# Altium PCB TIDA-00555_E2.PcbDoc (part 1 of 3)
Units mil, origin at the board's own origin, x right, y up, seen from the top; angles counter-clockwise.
Board outline 6490 x 3985 mil, 4 copper layers (Top Layer, MidLayer1, MidLayer2, Bottom Layer), stack 61.2 mil thick; 376 components, 194 nets, 936 pads, 294 vias.
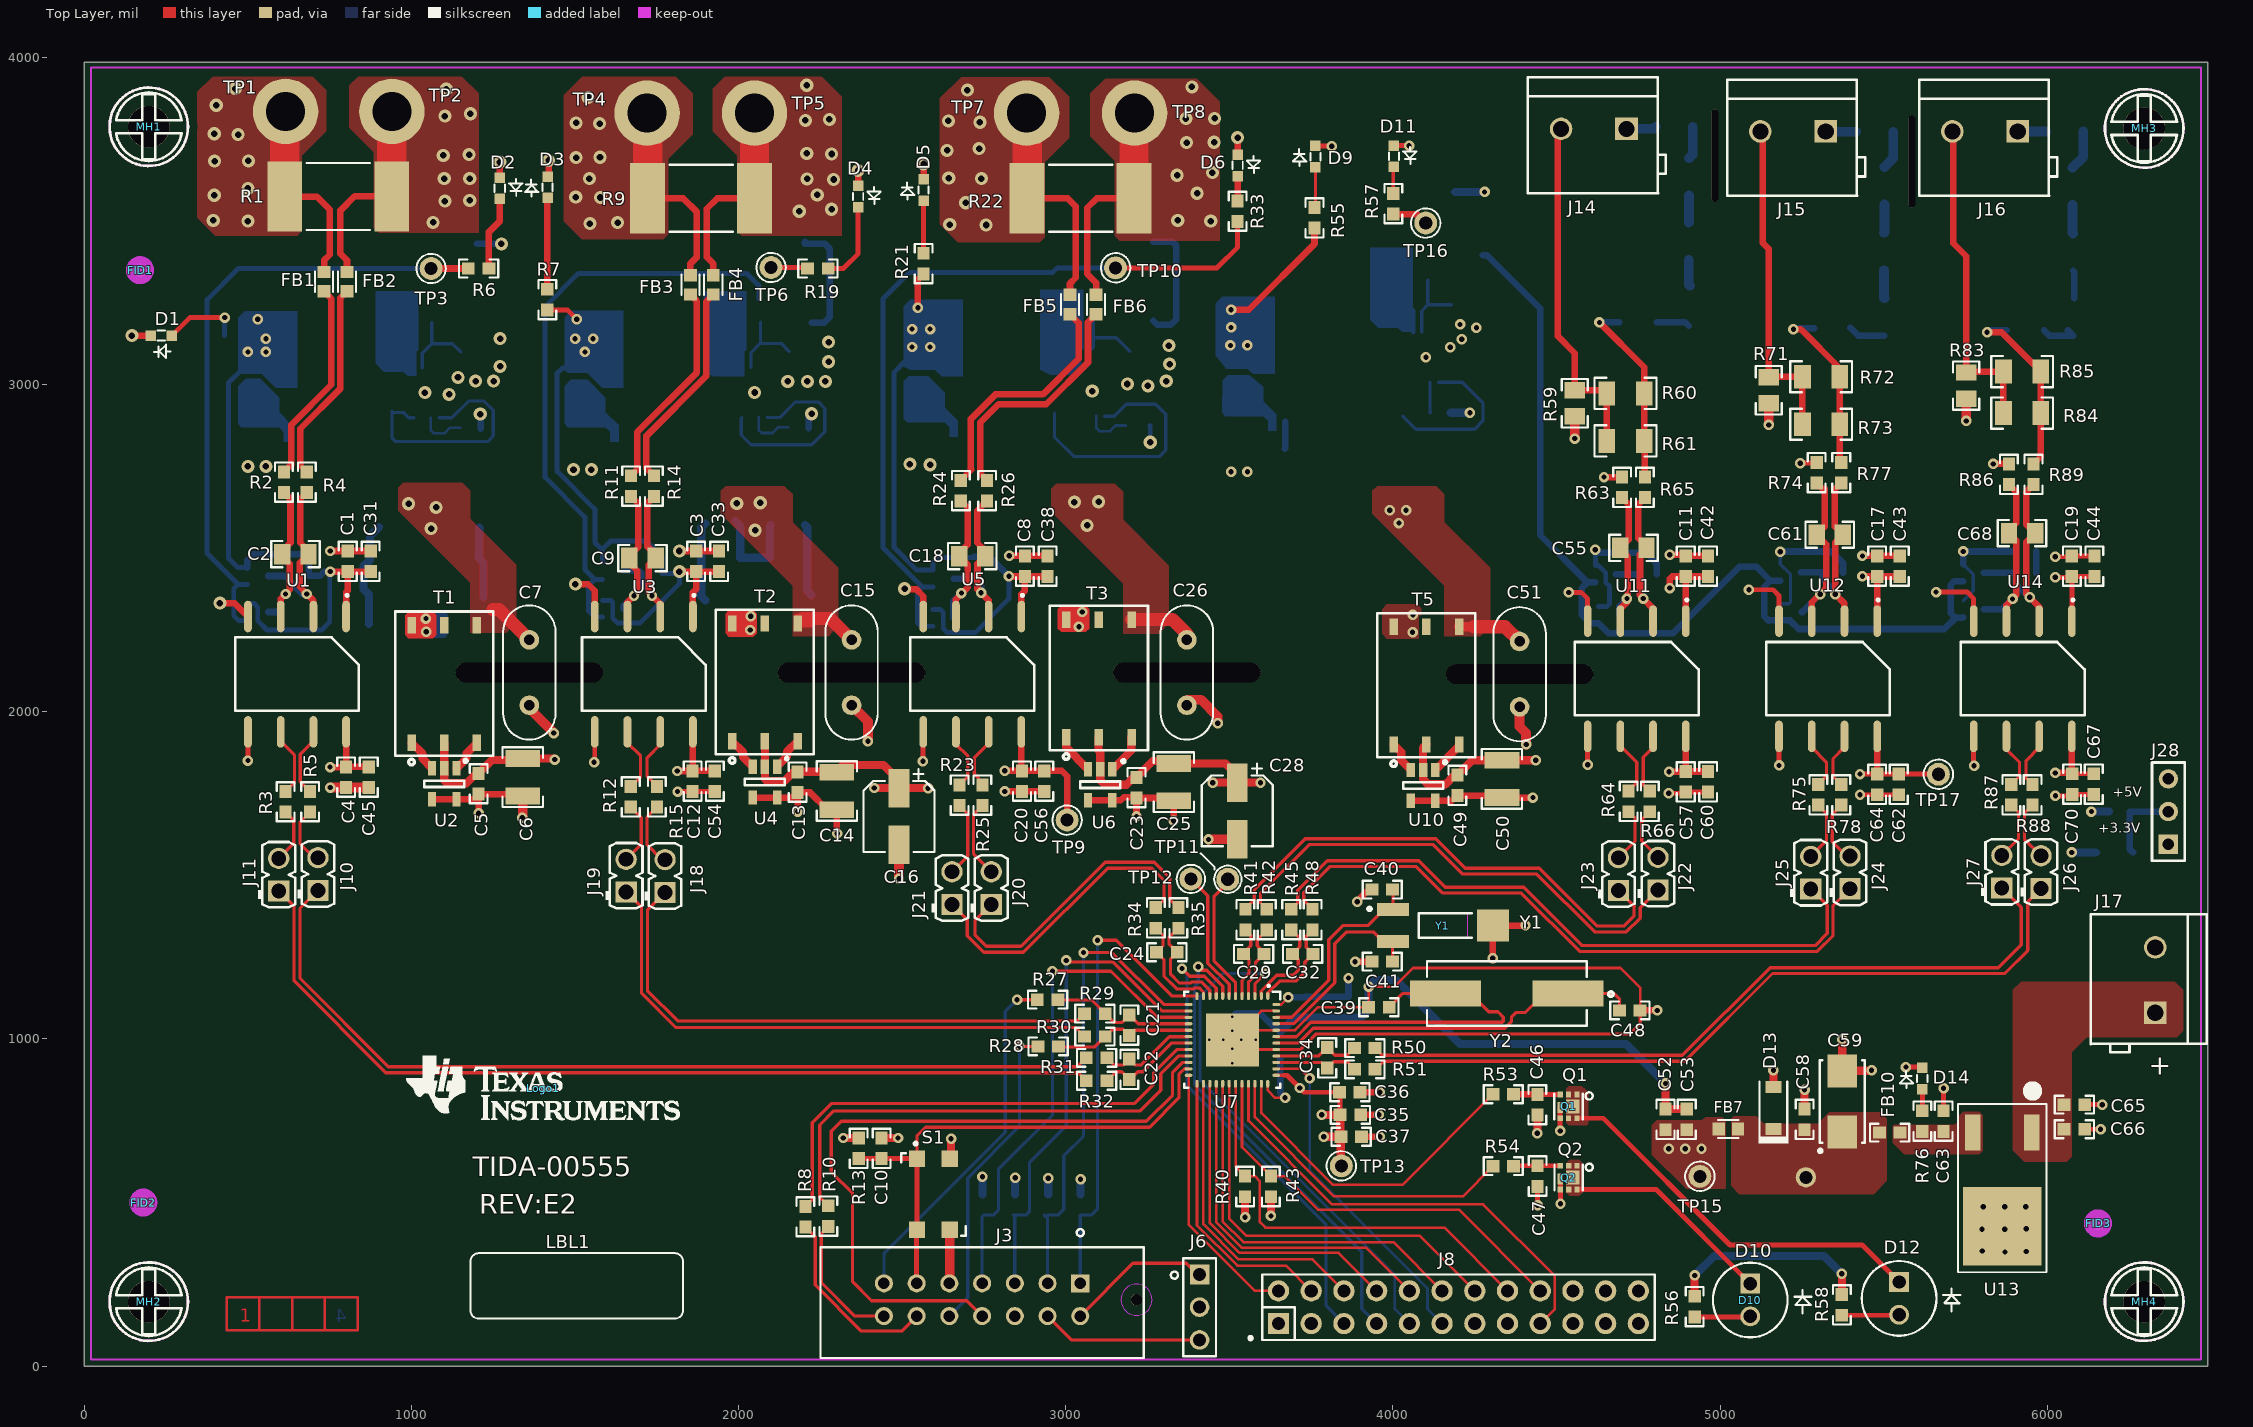
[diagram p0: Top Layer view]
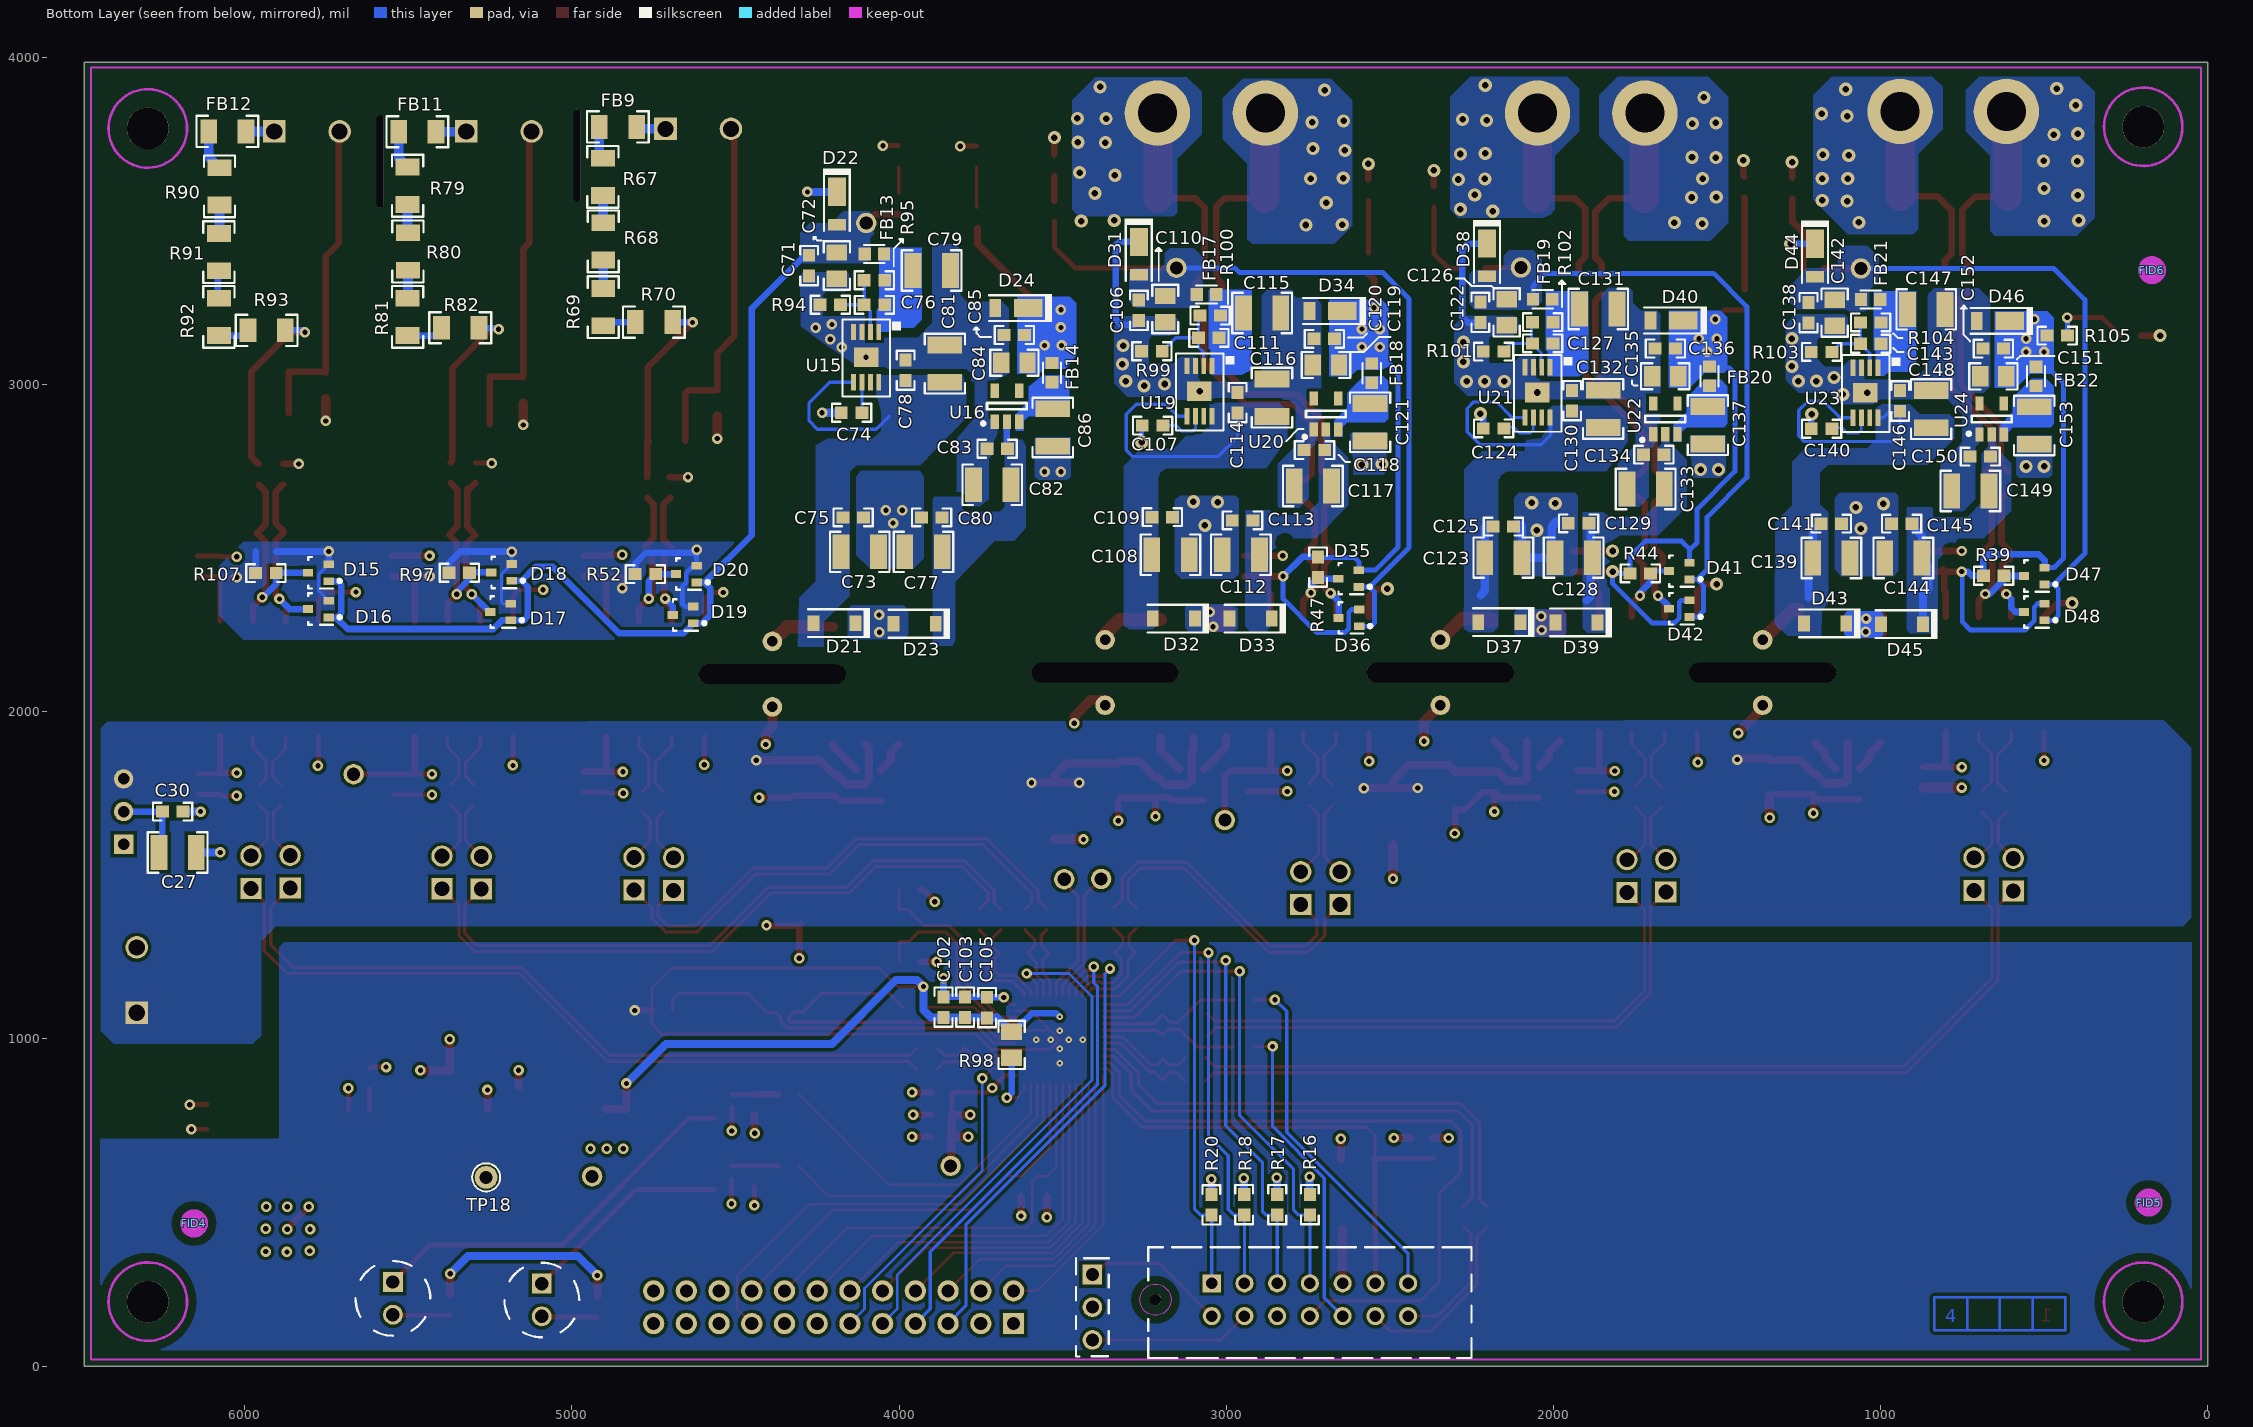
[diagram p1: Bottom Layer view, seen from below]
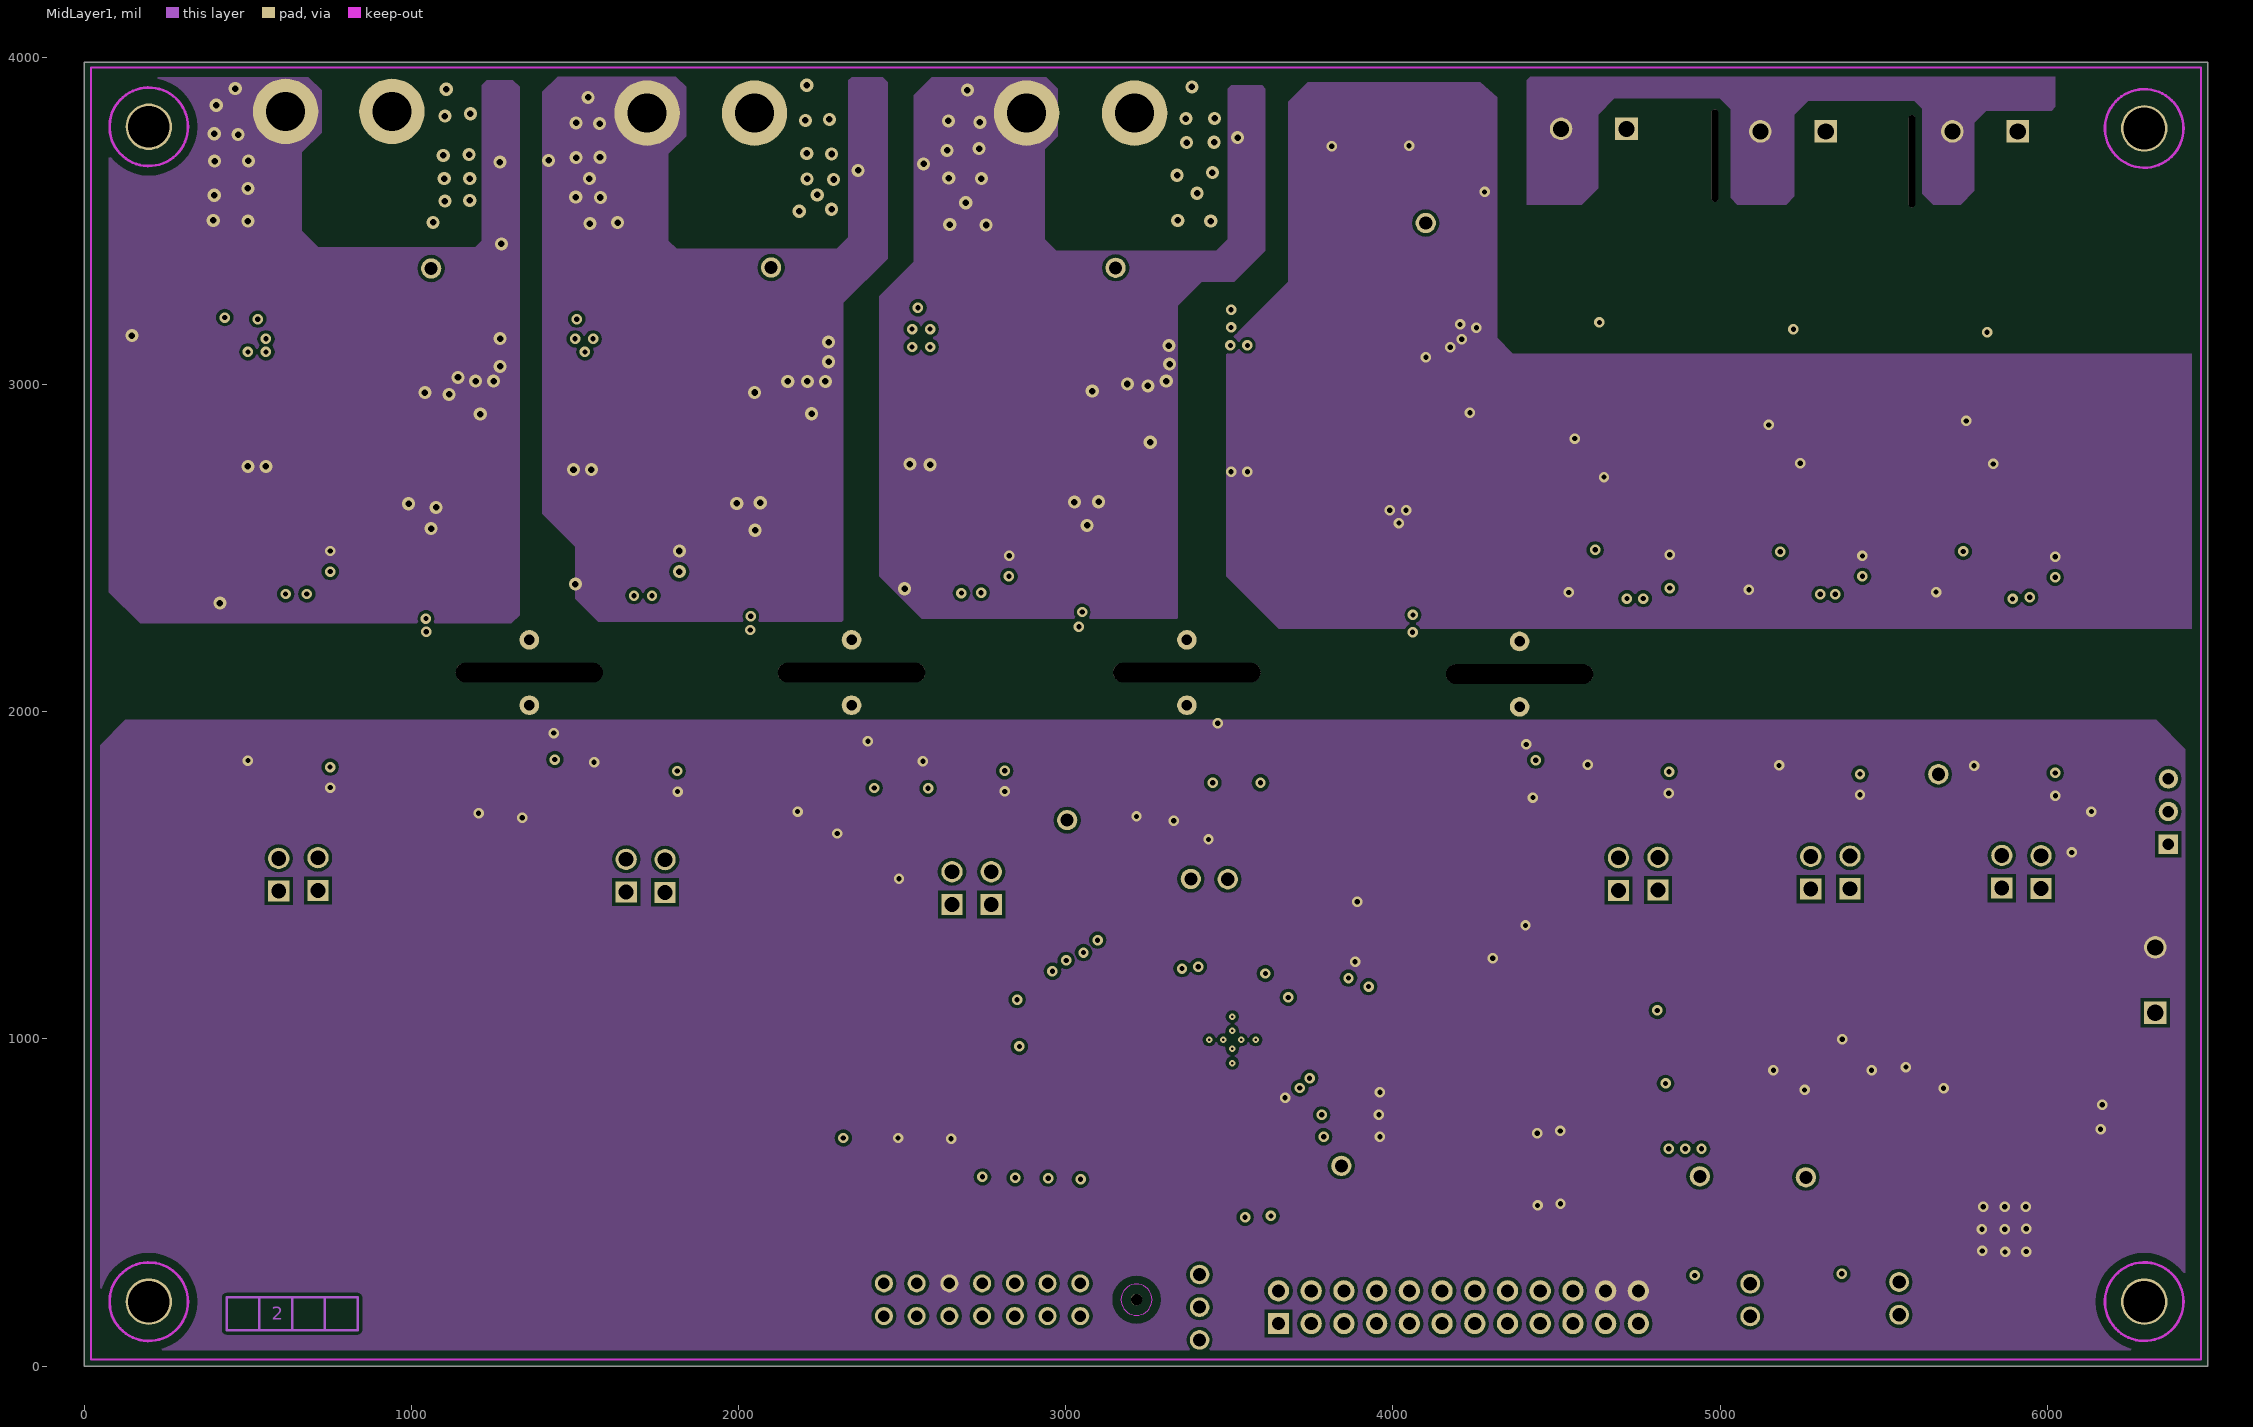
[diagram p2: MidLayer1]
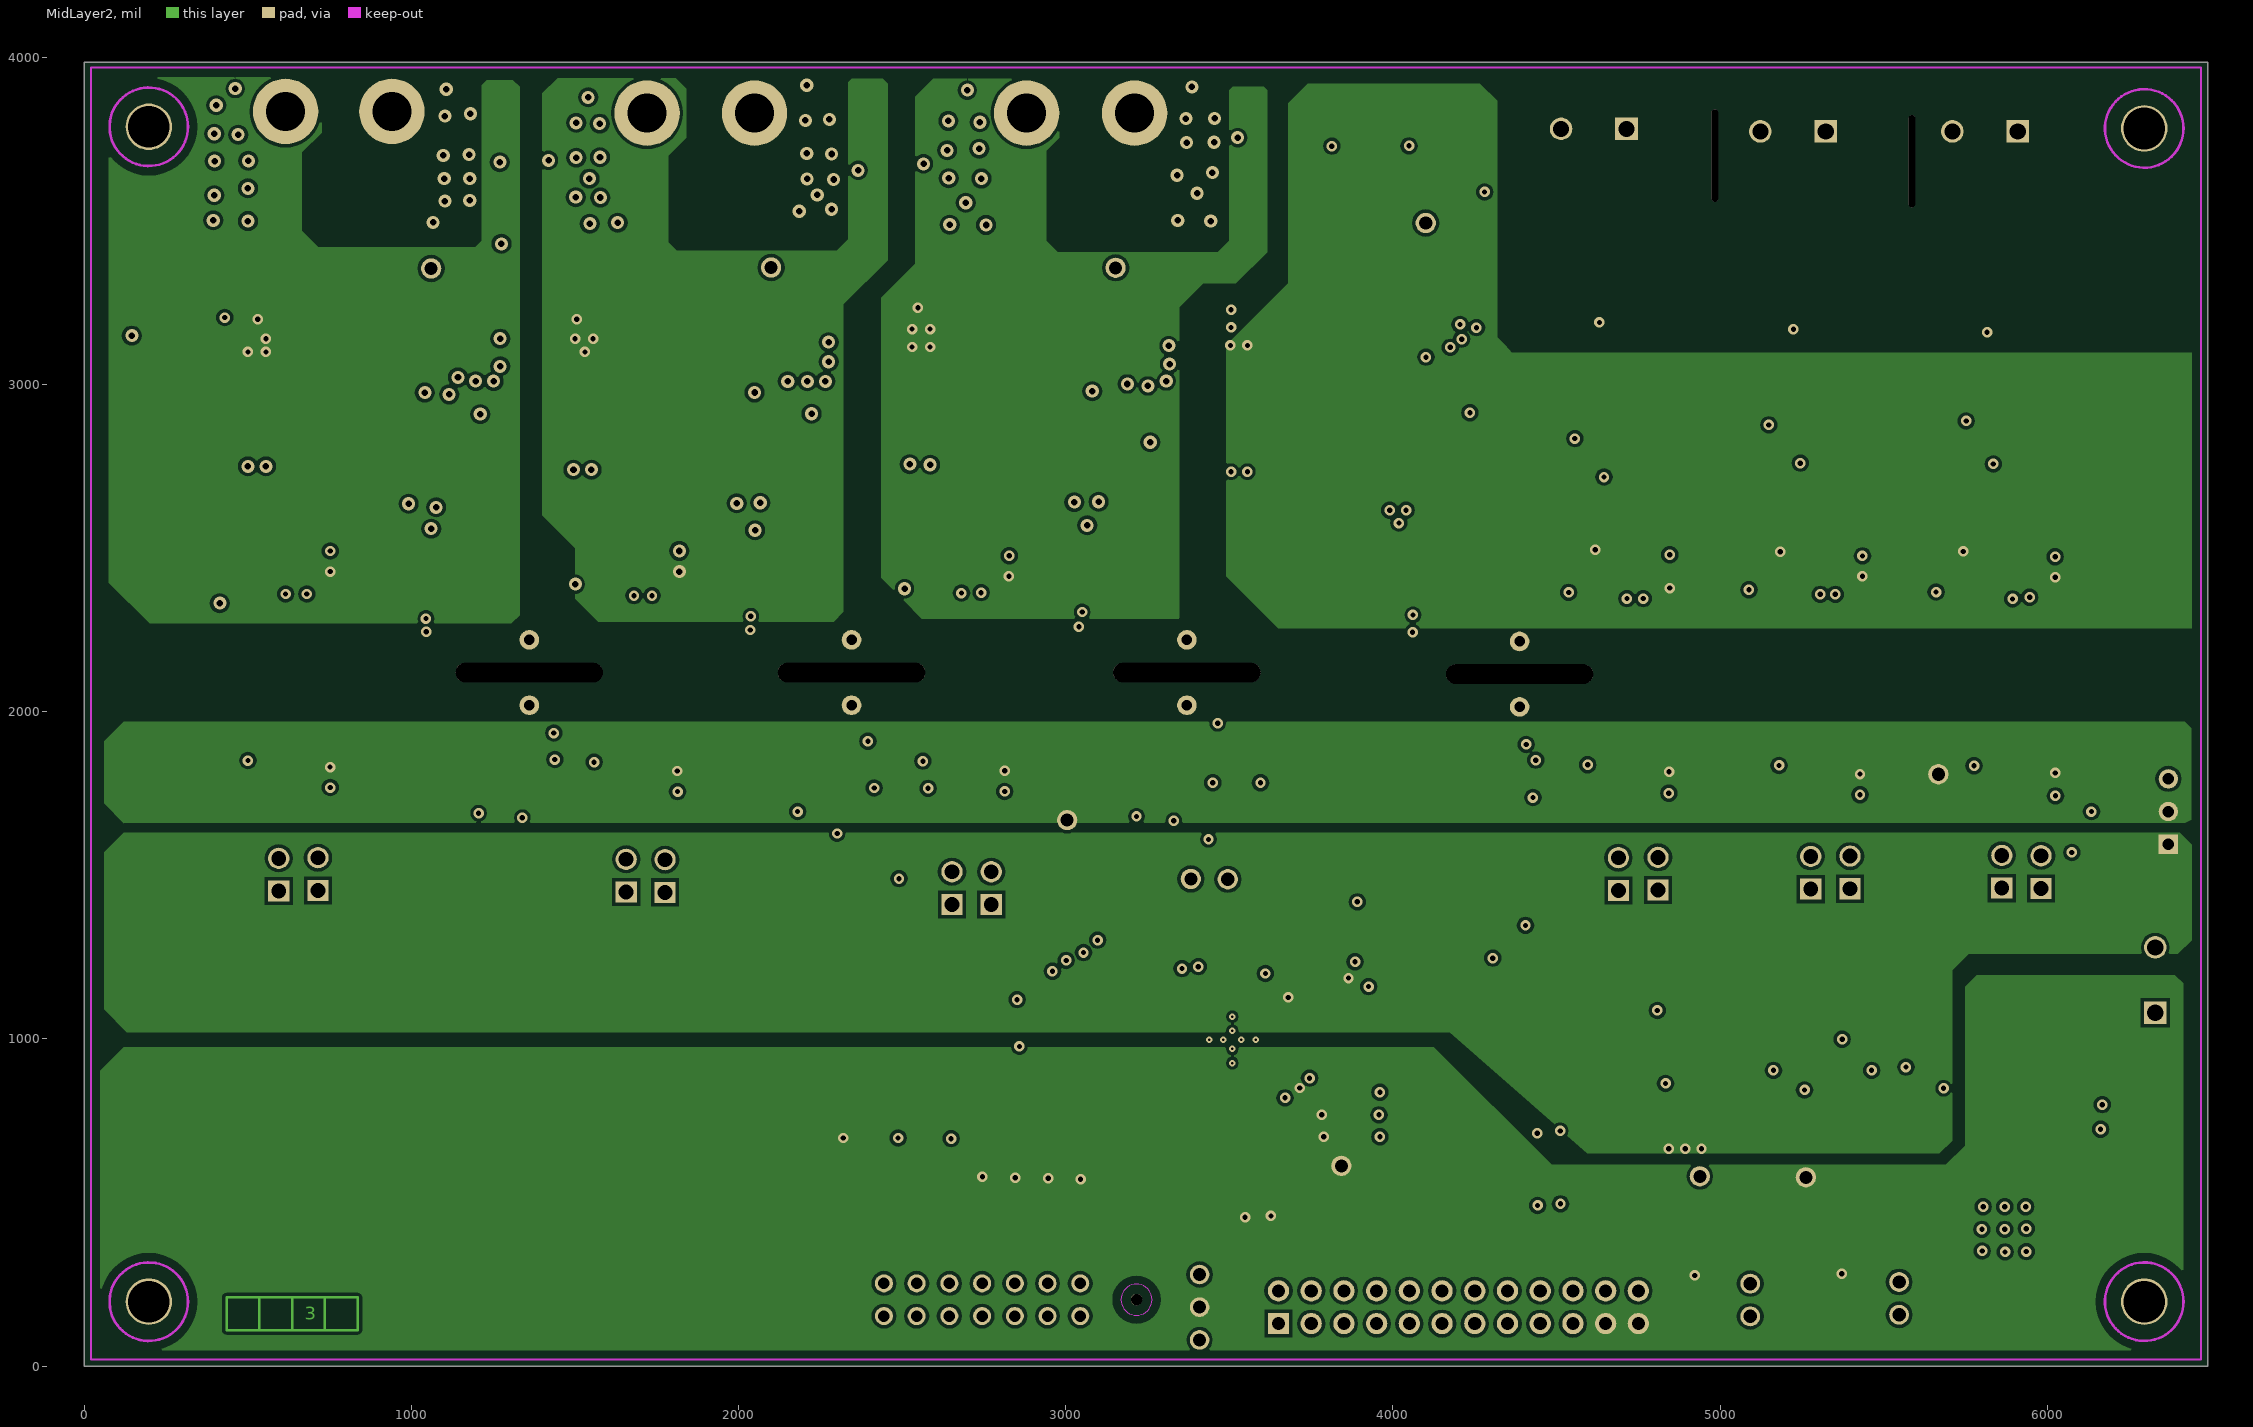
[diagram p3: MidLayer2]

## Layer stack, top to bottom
Top Solder: solder mask 0.4, Solder Resist, Dk 3.5
Top Layer: signal copper 2.8
Dielectric1: core 16.6, FR-4, Dk 4.8
MidLayer1: signal copper 2.8
Dielectric2: prepreg 16.8, FR-4, Dk 4.8
MidLayer2: signal copper 2.8
Dielectric3: core 16.6, FR-4, Dk 4.8
Bottom Layer: signal copper 2.8
Bottom Solder: solder mask 0.4, Solder Resist, Dk 3.5

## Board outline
0,0 0,3985 6490,3985 6490,0

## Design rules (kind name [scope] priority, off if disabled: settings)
AcuteAngle [All] p1 off: minimum=4.50000000000000E+0001 checktracksonly=FALSE
AssemblyTestPointUsage [All] p1 off: valid=2
AssemblyTestpoint [All] p1 off: testpointundercomponent=TRUE minsize=40 maxsize=100 preferedsize=60 minholesize=0 maxholesize=40 preferedholesize=32 testpointgrid=1 usegrid=TRUE gridtolerance=0.01 allowsidetop=TRUE allowsidebottom=TRUE
Clearance Clearance_2 [IsVia vs IsVia] p1: gap=8
Clearance "same net" [IsPad vs IsVia] p2: gap=5
Clearance Clearance_1 [InPolygon vs InPolygon] p3: gap=15
Clearance Clearance_BoardEdge_MountingHoles [OnCopper and InComponentClass('Mounting Holes') vs IsKeepOut] p4: gap=40
Clearance Clearance_BoardEdge_Poly [OnCopper and InPoly vs IsKeepOut] p5: gap=25
Clearance Clearance_Poly [InPolygon] p6: gap=10
Clearance [All] p7: gap=8
ComponentClearance ComponentClearance_Logo [InComponentClass('Logo')] p1 off: gap=50 collisioncheckmode=3 verticalgap=10 showdistances=FALSE
ComponentClearance ComponentClearance_ScrewToNut [(HasFootprint('NY PMS 440 0025 PH')) vs (HasFootprint('Keystone_1902C'))] p2 off: gap=5 collisioncheckmode=3 verticalgap=10 showdistances=FALSE
ComponentClearance ComponentClearance_MountingHoles [InComponentClass('Mounting Holes')] p3 off: gap=250 collisioncheckmode=3 verticalgap=100000 showdistances=FALSE
ComponentClearance ComponentClearance_SmallPassives [HasFootprint('0201*') or HasFootprint('0402*') or HasFootprint('0508') or HasFootprint('0603*') or HasFootprint('0612') or HasFootprint('0805*') or HasFootprint('0815*') or HasFootprint('0830*') or HasFootprint('1206*') or HasFootprint('1210*') or HasFootprint('1808*') or HasFootprint('1812*') or HasFootprint('1825*') or HasFootprint('2010*') or HasFootprint('2220*') or HasFootprint('2225*') or HasFootprint('2512*') or HasFootprint('2728*') or HasFootprint('3518*') vs HasFootprint('0201*') or HasFootprint('0402*') or HasFootprint('0508') or HasFootprint('0603*') or HasFootprint('0612') or HasFootprint('0805*') or HasFootprint('0815*') or HasFootprint('0830*') or HasFootprint('1206*') or HasFootprint('1210*') or HasFootprint('1808*') or HasFootprint('1812*') or HasFootprint('1825*') or HasFootprint('2010*') or HasFootprint('2220*') or HasFootprint('2225*') or HasFootprint('2512*') or HasFootprint('2728*') or HasFootprint('3518*')] p4 off: gap=20 collisioncheckmode=3 verticalgap=10 showdistances=FALSE
ComponentClearance ComponentClearance_THtoSMT [IsThruComponent vs IsSMTComponent] p5 off: gap=100 collisioncheckmode=3 verticalgap=30 showdistances=FALSE
ComponentClearance ComponentClearance_THtoTH [IsThruComponent vs IsThruComponent] p6 off: gap=118.11 collisioncheckmode=3 verticalgap=30 showdistances=FALSE
ComponentClearance [All] p7 off: gap=40 collisioncheckmode=3 verticalgap=10 showdistances=FALSE
DiffPairsRouting DiffPair_RS232DiffPairsRouting [InDifferentialPair ('RS232')] p1: maxlimit=8 minlimit=8 mostfreqgap=8 toplayer_minwidth=15 toplayer_maxwidth=15 toplayer_prefwidth=15 midlayer1_minwidth=15 midlayer1_maxwidth=15 midlayer1_prefwidth=15 midlayer2_minwidth=15 midlayer2_maxwidth=15 midlayer2_prefwidth=15 bottomlayer_minwidth=15 bottomlayer_maxwidth=15 bottomlayer_prefwidth=15 maxuncoupledlength=500
DiffPairsRouting [All] p2: maxlimit=100 minlimit=10 mostfreqgap=10 toplayer_minwidth=15 toplayer_maxwidth=15 toplayer_prefwidth=15 midlayer1_minwidth=15 midlayer1_maxwidth=15 midlayer1_prefwidth=15 midlayer2_minwidth=15 midlayer2_maxwidth=15 midlayer2_prefwidth=15 bottomlayer_minwidth=15 bottomlayer_maxwidth=15 bottomlayer_prefwidth=15 maxuncoupledlength=1000
FabricationTestPointUsage TestPointUsage [All] p1 off: valid=2 allowmultiple=FALSE
FabricationTestpoint Testpoint [All] p1 off: side=3 testpointundercomponent=TRUE minsize=40 maxsize=100 preferedsize=60 minholesize=0 maxholesize=40 preferedholesize=32 testpointgrid=1 allowsidetop=TRUE allowsidebottom=TRUE usegrid=TRUE gridtolerance=0.01
FanoutControl Fanout_LCC [IsLCC] p1 off: bgadir=Out bgaviamode=Centered fanoutstyle=Auto fanoutdirection=Alternating viagrid=1 // Fanout_LCC (Default Rule)
FanoutControl Fanout_BGA [IsBGA] p2 off: bgadir=Out bgaviamode=Centered fanoutstyle=Auto fanoutdirection=Alternating viagrid=1 // Fanout_BGA (Default Rule)
FanoutControl Fanout_SOIC [IsSOIC] p3 off: bgadir=Out bgaviamode=Centered fanoutstyle=Auto fanoutdirection=Alternating viagrid=1 // Fanout_SOIC (Default Rule)
FanoutControl Fanout_Default [All] p4 off: bgadir=Out bgaviamode=Centered fanoutstyle=Auto fanoutdirection=Alternating viagrid=1 // Fanout_Default (Default Rule)
FanoutControl Fanout_Small [(CompPinCount < 5)] p5 off: bgadir=Out bgaviamode=Centered fanoutstyle=Auto fanoutdirection=OutThenIn viagrid=1 // Fanout_Small (Default Rule)
Height [All] p1 off: minheight=0 maxheight=1000 prefheight=500
HoleSize [All] p1 off: absolutevalues=TRUE maxlimit=251 minlimit=8 maxpercent=80.000 minpercent=20.000
HoleToHoleClearance [All] p1 off: gap=10 allowstackedmicrovias=TRUE
LayerPairs [All] p1 off: enforce=TRUE
MatchedLengths DiffPair_RS232MatchedLengths [InDifferentialPair ('RS232')] p1: tolerance=1000 checknetsindiffpair=TRUE checkdiffpairvsdiffpair=TRUE checkothers=TRUE
MinimumAnnularRing MinimumAnnularRing_ThermalPadVias [IsVia and InAnyComponent] p1 off: minimumring=5.91
MinimumAnnularRing [All] p2 off: minimumring=8
MinimumSolderMaskSliver MinimumSolderMaskSliver_Logo [InComponentClass('Logo') vs InComponentClass('Logo')] p1 off: minsoldermaskwidth=0.7
MinimumSolderMaskSliver [All] p2 off: minsoldermaskwidth=3.94
NetAntennae [All] p1 off: netantennaetolerance=0
PasteMaskExpansion [All] p1 off: expansion=0
PlaneClearance [All] p1: clearance=15
PlaneConnect [All] p1: planeconnectstyle=Direct reliefexpansion=10 reliefentries=4 reliefconductorwidth=10 reliefairgap=10
PolygonConnect [All] p1: connectstyle=Direct reliefconductorwidth=10 reliefentries=4 polygonreliefangle="90 Angle" airgapwidth=10
RoutingCorners [All] p1 off: cornerstyle=45-Degree minsetback=100 maxsetback=100
RoutingLayers [All] p1 off: top layer_v5=TRUE mid layer 1_v5=TRUE mid layer 2_v5=TRUE bottom layer_v5=TRUE
RoutingPriority [All] p1 off: routingpriority=0
RoutingTopology [All] p1 off: topology=Shortest
RoutingVias ThermalPadVias [IsVia and InAnyComponent] p1: holewidth=16 width=32 viastyle="Through Hole" minholewidth=7.87 minwidth=19.68 maxholewidth=7.87 maxwidth=19.68
RoutingVias [All] p2: holewidth=16 width=32 viastyle="Through Hole" minholewidth=7.87 minwidth=19.68 maxholewidth=20 maxwidth=40
SMDToCorner [All] p1 off: distance=30000
SilkToSilkClearance [All] p1 off: silktosilkclearance=5
SilkToSolderMaskClearance SilkscreenOverComponentPads [IsPad] p1 off: minsilkscreentomaskgap=5 clearancetoexposedcopper=TRUE
SolderMaskExpansion [All] p1 off: expansion=1.97
UnpouredPolygon [All] p1: allowunpoured=FALSE
Width width-pwr [All] p1: maxlimit=100 minlimit=8 preferedwidth=15
Width [All] p2: maxlimit=100 minlimit=8 preferedwidth=8 checkconnectedcopper=TRUE
3 further rules are at their usual default settings.

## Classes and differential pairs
component class Header: J8 J10 J11 J18 J19 J20 J21 J22 J23 J24 J25 J26 J27
component class AssemblyNote: ZZ1 ZZ2 ZZ3 ZZ4
component class "Pg4-Current Sense": C1 C2 C3 C4 C8 C9 C12 C18 C20 C27 C30 C31 C33 C38 C45 C54 C56 D35 D36 D41 D42 D47 D48 FB1 FB2 FB3 FB4 FB5 FB6 J10 J11 J18 J19 J20 J21 J28 R1 R2 R3 R4 R5 R9 R11 R12 R14 R15 R22 R23 R24 R25 R26 R39 R44 R47 TP1 TP2 TP4 TP5 TP7 TP8 TP9 U1 U3 U5
component class Pg9-Hardware: FID1 FID2 FID3 FID4 FID5 FID6 LBL1 Logo1 MH1 MH2 MH3 MH4 ZZ1 ZZ2 ZZ3 ZZ4
component class FiducialMark: FID1 FID2 FID3 FID4 FID5 FID6
component class "Pg7-Power supply 2": C5 C6 C7 C13 C14 C15 C16 C122 C123 C124 C125 C126 C127 C128 C129 C130 C131 C132 C133 C134 C135 C136 C137 C138 C139 C140 C141 C142 C143 C144 C145 C146 C147 C148 C149 C150 C151 C152 C153 D1 D2 D3 D4 D37 D38 D39 D40 D43 D44 D45 D46 FB19 FB20 FB21 FB22 R6 R7 R19 R101 R102 R103 R104 R105 T1 T2 TP3 TP6 U2 U4 U21 U22 U23 U24
component class Label: LBL1
component class Logo: Logo1
component class "Mounting Holes": MH1 MH2 MH3 MH4
component class Pg3-Microcontroller: C21 C22 C24 C29 C32 C34 C35 C36 C37 C39 C40 C41 C48 C52 C53 C102 C103 C105 FB7 J8 R27 R28 R29 R30 R31 R32 R34 R35 R40 R41 R42 R43 R45 R48 R50 R51 R98 TP11 TP12 TP13 TP15 U7 Y1 Y2
component class "Pg5-Voltage signal condtioning": C11 C17 C19 C42 C43 C44 C55 C57 C60 C61 C62 C64 C67 C68 C70 D15 D16 D17 D18 D19 D20 FB9 FB11 FB12 J14 J15 J16 J22 J23 J24 J25 J26 J27 R52 R59 R60 R61 R63 R64 R65 R66 R67 R68 R69 R70 R71 R72 R73 R74 R75 R77 R78 R79 R80 R81 R82 R83 R84 R85 R86 R87 R88 R89 R90 R91 R92 R93 R97 R107 TP17 U11 U12 U14
component class "Pg8.JTAG Interface + LEDs + Decoupling Capacitors": C10 C46 C47 C58 C59 C63 C65 C66 D10 D12 D13 D14 FB10 J3 J6 J17 Q1 Q2 R8 R10 R13 R16 R17 R18 R20 R53 R54 R56 R58 R76 S1 TP18 U13
component class "Pg6-Power supply 1": C23 C25 C26 C28 C49 C50 C51 C71 C72 C73 C74 C75 C76 C77 C78 C79 C80 C81 C82 C83 C84 C85 C86 C106 C107 C108 C109 C110 C111 C112 C113 C114 C115 C116 C117 C118 C119 C120 C121 D5 D6 D9 D11 D21 D22 D23 D24 D31 D32 D33 D34 FB13 FB14 FB17 FB18 R21 R33 R55 R57 R94 R95 R99 R100 T3 T5 TP10 TP16 U6 U10 U15 U16 U19 U20

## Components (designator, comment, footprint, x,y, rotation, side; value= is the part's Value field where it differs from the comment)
C1 "" 0603 805,2460 r90 top (schematic designator C127)
C2 "08055A331KAT2A" 0805_HV#1 645,2482 r180 top (schematic designator C17)
C3 "" 0603 1870,2460 r90 top (schematic designator C4)
C4 "" 0603 800,1800 r90 top (schematic designator C3)
C5 "" 0603 1205,1780 r90 top (schematic designator C26)
C6 "" 1210#1 1340,1800 r90 top (schematic designator C24)
C7 "" CAP_200mil#1 1360,2120 r90 top (schematic designator C22)
C8 "" 0603 2875,2445 r90 top (schematic designator C7)
C9 "08055A331KAT2A" 0805_HV#1 1706,2470 r180 top (schematic designator C17)
C10 "06035A102KAT2A" 0603 2436.76,665.73 r90 top (schematic designator C77)
C11 "" 0603 4895,2445 r90 top (schematic designator C13)
C12 "" 0603 1859,1788 r90 top (schematic designator C24)
C13 "" 0603 2180,1785 r90 top (schematic designator C27)
C14 "" 1210#1 2300,1757.91 r90 top (schematic designator C25)
C15 "" CAP_200mil#1 2345,2120 r90 top (schematic designator C23)
C16 "UUD1E220MCL1GS" SM_RADIAL_5MM 2490,1680 r270 top (schematic designator C32)
C17 "" 0603 5480,2445 r90 top (schematic designator C2)
C18 "08055A331KAT2A" 0805_HV#1 2714,2476 r180 top (schematic designator C9)
C19 "" 0603 6075,2445 r90 top (schematic designator C15)
C20 "" 0603 2866,1788 r90 top (schematic designator C136)
C21 "C0603C101J5GAC" 0603 3194,1042.15 r90 top (schematic designator C22)
C22 "C0603C101J5GAC" 0603 3194,907.15 r90 top (schematic designator C23)
C23 "" 0603 3216,1768 r90 top (schematic designator C105)
C24 "C0603C101J5GAC" 0603 3309,1264.96 r0 top (schematic designator C18)
C25 "" 1210#1 3330,1785 r90 top (schematic designator C102)
C26 "" CAP_200mil#2 3370,2120 r90 top (schematic designator C98)
C27 "" 1210#2 6205,1570 r180 bottom
C28 "UUD1E220MCL1GS" SM_RADIAL_5MM 3524,1697 r270 top (schematic designator C96)
C29 "C0603C101J5GAC" 0603 3574,1259.98 r0 top (schematic designator C20)
C30 "" 0603 6220,1695 r180 bottom
C31 "GRM188R71C105KA12D" 0603 875,2460 r270 top
C32 "C0603C101J5GAC" 0603 3724,1259.98 r0 top (schematic designator C8)
C33 "GRM188R71C105KA12D" 0603 1940,2460 r270 top
C34 "C0603C101J5GAC" 0603 3799,942.15 r270 top (schematic designator C19)
C35 "GRM188R71C105KA12D" 0603 3870,768 r0 top (schematic designator C7)
C36 "0603YC104JAT2A" 0603 3868,837 r0 top (schematic designator C10)
C37 "GRM188R61E106MA73" 0603 3872,701 r0 top (schematic designator C142)
C38 "GRM188R71C105KA12D" 0603 2944,2445 r270 top
C39 "GRM1885C1H180JA01D" 0603 3957,1097 r180 top (schematic designator C66)
C40 "06035A120JAT2A" 0603 3967.11,1456.55 r180 top (schematic designator C78)
C41 "06035A120JAT2A" 0603 3967.11,1236.55 r180 top (schematic designator C89)
C42 "GRM188R71C105KA12D" 0603 4963,2445 r270 top
C43 "GRM188R71C105KA12D" 0603 5549,2445 r270 top
C44 "GRM188R71C105KA12D" 0603 6144,2445 r270 top
C45 "GRM188R71C105KA12D" 0603 869,1800 r270 top
C46 "06033C104JAT2A" 0603 4441.59,798.78 r270 top (schematic designator C71)
C47 "06033C104JAT2A" 0603 4442,581 r270 top (schematic designator C72)
C48 "GRM1885C1H180JA01D" 0603 4724,1087 r0 top (schematic designator C69)
C49 "" 0603 4197,1775.22 r90 top (schematic designator C70)
C50 "" 1210#1 4332.8,1795 r90 top (schematic designator C67)
C51 "" CAP_200mil#2 4387,2115 r90 top (schematic designator C63)
C52 "06033C104JAT2A" 0603 4833,754 r90 top (schematic designator C144)
C53 "0603ZD475KAT2A" 0603 4898,754 r90 top (schematic designator C139)
C54 "GRM188R71C105KA12D" 0603 1927,1788 r270 top
C55 "08055A331KAT2A" 0805_HV#1 4735,2501 r180 top (schematic designator C147)
C56 "GRM188R71C105KA12D" 0603 2934,1788 r270 top
C57 "" 0603 4895,1786 r90 top (schematic designator C8)
C58 "C0603C104K5RACTU" 0603 5258,754 r90 top (schematic designator C29)
C59 "293D475X9035C2TE3" 6032-28 5373,809 r90 top (schematic designator C28)
C60 "GRM188R71C105KA12D" 0603 4963,1786 r270 top
C61 "08055A331KAT2A" 0805_HV#1 5335,2541 r180 top (schematic designator C151)
C62 "GRM188R71C105KA12D" 0603 5546,1778 r270 top
C63 "GRM188R71C105KA12D" 0603 5683,749 r90 top (schematic designator C27)
C64 "" 0603 5480,1778 r90 top (schematic designator C149)
C65 "GRM188R71C105KA12D" 0603 6083,799 r0 top (schematic designator C25)
C66 "C0603C104K5RACTU" 0603 6083,724 r0 top (schematic designator C26)
C67 "GRM188R71C105KA12D" 0603 6142,1779 r270 top
C68 "08055A331KAT2A" 0805_HV#1 5922.73,2545.98 r180 top (schematic designator C155)
C70 "" 0603 6076,1779 r90 top (schematic designator C153)
C71 "" 0603 4275,3364 r270 bottom (schematic designator C90)
C72 "" 0805_HV#2 4190,3364 r90 bottom (schematic designator C84)
C73 "" 1210#2 4120,2489 r0 bottom (schematic designator C199)
C74 "" 0603 4145,2914 r180 bottom (schematic designator C161)
C75 "" 0603 4140,2594 r0 bottom (schematic designator C157)
C76 "" 0603 4075,3244 r0 bottom (schematic designator C160)
C77 "" 1210#2 3925,2489 r0 bottom (schematic designator C197)
C78 "" 0603 3980,3044 r90 bottom (schematic designator C159)
C79 "" 1210#2 3900,3349 r0 bottom (schematic designator C92)
C80 "" 0603 3900,2594 r0 bottom (schematic designator C198)
C81 "" 1210#2 3860,3064 r270 bottom (schematic designator C158)
C82 "" 1210#2 3715,2694 r180 bottom (schematic designator C107)
C83 "" 0603 3700,2804 r0 bottom (schematic designator C109)
C84 "" 0805_HV#2 3647.4,3066.76 r180 bottom (schematic designator C103)
C85 "" 0603 3647.4,3151.76 r0 bottom (schematic designator C106)
C86 "" 1210#2 3530,2869 r90 bottom (schematic designator C108)
C102 "GRM188R61E106MA73" 0603 3864,1097 r270 bottom (schematic designator C141)
C103 "GRM188R71C105KA12D" 0603 3798,1097 r270 bottom (schematic designator C73)
C105 "0603YC104JAT2A" 0603 3731,1096 r270 bottom (schematic designator C74)
C106 "" 0603 3267,3227 r270 bottom (schematic designator C146)
C107 "" 0603 3225,2875 r180 bottom (schematic designator C148)
C108 "" 1210#2 3170,2480 r0 bottom (schematic designator C196)
C109 "" 0603 3195,2595 r0 bottom (schematic designator C19)
C110 "" 0805_HV#2 3186,3231 r90 bottom (schematic designator C143)
C111 "" 0603 3053,3143 r180 bottom (schematic designator C145)
C112 "" 1210#2 2955,2480 r0 bottom (schematic designator C101)
C113 "" 0603 2950,2585 r0 bottom (schematic designator C195)
C114 "" 0603 2965,2945 r90 bottom (schematic designator C144)
C115 "" 1210#2 2890,3219 r0 bottom (schematic designator C147)
C116 "" 1210#2 2860,2960 r270 bottom (schematic designator C200)
C117 "" 1210#2 2735,2690 r180 bottom (schematic designator C151)
C118 "" 0603 2730,2800 r0 bottom (schematic designator C153)
C119 "" 0805_HV#2 2695,3060 r180 bottom (schematic designator C149)
C120 "" 0603 2700,3140 r0 bottom (schematic designator C150)
C121 "" 1210#2 2560,2885 r90 bottom (schematic designator C152)
C122 "" 0603 2222.64,3221 r270 bottom (schematic designator C46)
C123 "" 1210#2 2152.64,2471 r0 bottom (schematic designator C35)
C124 "" 0603 2182.64,2866 r180 bottom (schematic designator C50)
C125 "" 0603 2152.64,2566 r0 bottom (schematic designator C36)
C126 "" 0805_HV#2 2142.64,3221 r90 bottom (schematic designator C40)
C127 "" 0603 2032.64,3126 r180 bottom (schematic designator C45)
C128 "" 1210#2 1937.64,2471 r0 bottom (schematic designator C30)
C129 "" 0603 1922.64,2576 r0 bottom (schematic designator C31)
C130 "" 0603 1942.64,2951 r90 bottom (schematic designator C44)
C131 "" 1210#2 1862.64,3231 r0 bottom (schematic designator C48)
C132 "" 1210#2 1847.64,2926 r270 bottom (schematic designator C39)
C133 "" 1210#2 1717.64,2681 r180 bottom (schematic designator C57)
C134 "" 0603 1692.64,2786 r0 bottom (schematic designator C60)
C135 "" 0805_HV#2 1657.64,3025.5 r180 bottom (schematic designator C52)
C136 "" 0603 1657.64,3110.5 r0 bottom (schematic designator C54)
C137 "" 1210#2 1527.64,2876 r90 bottom (schematic designator C58)
C138 "" 0603 1220,3220 r270 bottom (schematic designator C43)
C139 "" 1210#2 1150,2470 r0 bottom (schematic designator C33)
C140 "" 0603 1180,2865 r180 bottom (schematic designator C49)
C141 "" 0603 1150,2575 r0 bottom (schematic designator C34)
C142 "" 0805_HV#2 1140,3220 r90 bottom (schematic designator C38)
C143 "" 0603 1030,3125 r180 bottom (schematic designator C42)
C144 "" 1210#2 930,2470 r0 bottom (schematic designator C28)
C145 "" 0603 935,2575 r0 bottom (schematic designator C29)
C146 "" 0603 940,2950 r90 bottom (schematic designator C41)
C147 "" 1210#2 860,3230 r0 bottom (schematic designator C47)
C148 "" 1210#2 845,2925 r270 bottom (schematic designator C37)
C149 "" 1210#2 725,2675 r180 bottom (schematic designator C55)
C150 "" 0603 695,2780 r0 bottom (schematic designator C59)
C151 "" 0805_HV#2 655,3025.32 r180 bottom (schematic designator C51)
C152 "" 0603 655,3110.32 r0 bottom (schematic designator C53)
C153 "" 1210#2 530,2875 r90 bottom (schematic designator C56)
D1 "" LED0603AA 235,3150 r0 top (schematic designator D17)
D2 "" LED0603AA 1270,3600 r90 top (schematic designator D13)
D3 "" LED0603AA 1415.75,3603.58 r270 top (schematic designator D18)
D4 "" LED0603AA 2365,3575 r90 top (schematic designator D14)
D5 "" LED0603AA 2565,3595 r270 top (schematic designator D49)
D6 "" LED0603AA 3525,3670 r90 top (schematic designator D22)
D9 "" LED0603AA 3763,3697.02 r270 top (schematic designator D34)
D10 "TLHR6405" LED_5MM 5092,202 r90 top (schematic designator D44)
D11 "" LED0603AA 4003,3698 r90 top (schematic designator D28)
D12 "TLHR6405" LED_5MM 5547,207 r90 top (schematic designator D43)
D13 "MMSZ5228B-7-F" SOD-123#1 5163,789 r90 top (schematic designator D47)
D14 "LED_LG L29K-G2J1-24-Z" LED0603AA 5618,879 r270 top (schematic designator D46)
D15 "" SOT-323 5775,2425 r0 bottom (schematic designator D41)
D16 "" SOT-323 5775,2314 r0 bottom (schematic designator D42)
D17 "" SOT-323 5218,2305 r0 bottom (schematic designator D6)
D18 "" SOT-323 5215,2426 r0 bottom (schematic designator D4)
D19 "" SOT-323 4660,2296 r0 bottom (schematic designator D5)
D20 "" SOT-323 4650,2421 r0 bottom (schematic designator D35)
D21 "MBR0520L" SOD-123#2 4197,2271 r0 bottom (schematic designator D24)
D22 "" powerDI123 4190,3539 r270 bottom (schematic designator D26)
D23 "MBR0520L" SOD-123#2 3952,2269 r0 bottom (schematic designator D21)
D24 "" powerDI123 3655,3234 r0 bottom (schematic designator D31)
D31 "" powerDI123 3267,3386 r270 bottom (schematic designator D20)
D32 "MBR0520L" SOD-123#2 3160,2285 r0 bottom (schematic designator D30)
D33 "MBR0520L" SOD-123#2 2925,2285 r0 bottom
D34 "" powerDI123 2695,3225 r0 bottom (schematic designator D48)
D35 "" SOT-323 2626,2407 r0 bottom (schematic designator D52)
D36 "" SOT-323 2625,2287 r0 bottom (schematic designator D53)
D37 "MBR0520L" SOD-123#2 2165,2274 r0 bottom (schematic designator D10)
D38 "" powerDI123 2202.64,3381 r270 bottom (schematic designator D12)
D39 "MBR0520L" SOD-123#2 1929,2273 r0 bottom (schematic designator D8)
D40 "" powerDI123 1652.64,3196 r0 bottom (schematic designator D16)
D41 "" SOT-323 1615,2430 r0 bottom (schematic designator D84)
D42 "" SOT-323 1615,2315 r0 bottom (schematic designator D85)
D43 "MBR0520L" SOD-123#2 1169,2270 r0 bottom (schematic designator D9)
D44 "" powerDI123 1200,3380 r270 bottom (schematic designator D11)
D45 "MBR0520L" SOD-123#2 934,2268 r0 bottom (schematic designator D7)
D46 "" powerDI123 655,3195 r0 bottom (schematic designator D15)
D47 "" SOT-323 530,2415 r0 bottom (schematic designator D1)
D48 "" SOT-323 530,2305 r0 bottom (schematic designator D2)
FB1 "MMZ1608B102C" FB0603#1 732.68,3315 r270 top (schematic designator FB17)
FB2 "MMZ1608B102C" FB0603#1 802.68,3315 r270 top
FB3 "MMZ1608B102C" FB0603#1 1852.32,3305 r270 top (schematic designator FB19)
FB4 "MMZ1608B102C" FB0603#1 1922.32,3305 r270 top (schematic designator FB20)
FB5 "MMZ1608B102C" FB0603#1 3012.69,3245 r270 top (schematic designator FB17)
FB6 "MMZ1608B102C" FB0603#1 3092.69,3245 r270 top (schematic designator FB21)
FB7 "MMZ1608B102C" FB0603#1 5025,725 r180 top
FB9 "ERJ-8ENF3323V" 1206 4859,3788 r0 bottom (schematic designator FB18)
FB10 "1000 OHM" 0603 5518,714 r180 top (schematic designator FB21)
FB11 "ERJ-8ENF3323V" 1206 5472,3773 r0 bottom (schematic designator FB19)
FB12 "ERJ-8ENF3323V" 1206 6053,3774 r0 bottom (schematic designator FB20)
FB13 "" FB0603#2 4075,3399 r0 bottom (schematic designator FB6)
FB14 "" FB0603#2 3532.4,3036.76 r90 bottom (schematic designator FB9)
FB17 "" FB0603#2 3060,3275 r0 bottom (schematic designator FB8)
FB18 "" FB0603#2 2555,3035 r90 bottom (schematic designator FB22)
FB19 "" FB0603#2 2032.64,3261 r0 bottom (schematic designator FB2)
FB20 "" FB0603#2 1523,3026 r90 bottom (schematic designator FB4)
FB21 "" FB0603#2 1030,3260 r0 bottom (schematic designator FB1)
FB22 "" FB0603#2 525,3025 r90 bottom (schematic designator FB3)
FID1 "" Fiducial10-20#1 170,3350 r0 top (schematic designator FID2)
FID2 "" Fiducial10-20#1 180,500 r0 top (schematic designator FID1)
FID3 "" Fiducial10-20#2 6155,436 r90 top
FID4 "" Fiducial10-20#2 6155,436 r90 bottom
FID5 "" Fiducial10-20#1 180,500 r180 bottom
FID6 "" Fiducial10-20#1 170,3350 r180 bottom (schematic designator FID8)
J3 "N2514-6002-RB" 3M_N2514-6002-RB 2744,203 r180 top (schematic designator J34)
J6 "68001-403HLF" HDR1X3#1 3409,180 r0 top (schematic designator J33)
J8 "67997-424HLF" TSW-112-07-G-D 4200,180 r0 top (schematic designator J14)
J10 "61300211121" WURTH_61300211121 714,1504 r90 top (schematic designator J42)
J11 "61300211121" WURTH_61300211121 594,1502 r90 top (schematic designator J40)
J14 "ED120/2DS" CONN_ED120-2DS 4613.72,3782 r90 top (schematic designator J44)
J15 "ED120/2DS" CONN_ED120-2DS 5222.72,3774 r90 top (schematic designator J48)
J16 "ED120/2DS" CONN_ED120-2DS 5809.72,3774 r90 top (schematic designator J9)
J17 "ED120/2DS" CONN_ED120-2DS 6330,1180 r0 top (schematic designator J10)
J18 "61300211121" WURTH_61300211121 1775,1498 r90 top
J19 "61300211121" WURTH_61300211121 1656,1499 r90 top
J20 "61300211121" WURTH_61300211121 2772,1461 r90 top
J21 "61300211121" WURTH_61300211121 2652,1461 r90 top
J22 "61300211121" WURTH_61300211121 4810,1505 r90 top
J23 "61300211121" WURTH_61300211121 4689,1504 r90 top
J24 "61300211121" WURTH_61300211121 5397,1509 r90 top
J25 "61300211121" WURTH_61300211121 5277,1508 r90 top
J26 "61300211121" WURTH_61300211121 5981,1510 r90 top
J27 "61300211121" WURTH_61300211121 5861,1511 r90 top
J28 "68001-403HLF" HDR1X3#2 6370,1595 r90 top
LBL1 "" Label_650x200 1505,245 r180 top
Logo1 "" TI_STACKED_SOLDERMASK_SMALL 1402,850 r0 top
MH1 "" MH3.2 196.85,3788.19 r0 top (schematic designator MH4)
MH2 "" MH3.2 196.85,196.85 r0 top (schematic designator MH1)
MH3 "" MH3.2 6296.32,3783.19 r0 top (schematic designator MH2)
MH4 "" MH3.2 6296.32,196.85 r0 top (schematic designator MH3)
Q1 "CSD17571Q2" SON_CSD17571Q2 4536.59,793.78 r180 top (schematic designator Q2)
Q2 "CSD17571Q2" SON_CSD17571Q2 4537,576 r180 top (schematic designator Q1)
R1 "WSLP39213L000FEB" RC3921 776,3575 r0 top (schematic designator R100)
R2 "RC0603FR-0712RL" 0603 610,2702 r270 top (schematic designator R127)
R3 "" 0603 615,1725 r270 top (schematic designator R8)
R4 "RC0603FR-0712RL" 0603 680,2702 r270 top (schematic designator R99)
R5 "" 0603 690,1725 r270 top (schematic designator R7)
R6 "" 0603 1205,3355 r180 top (schematic designator R34)
R7 "" 0603 1415,3260 r270 top (schematic designator R41)
R8 "CRCW06030000Z0EA" 0603 2204,456.5 r90 top (schematic designator R93)
R9 "WSLP39213L000FEB" RC3921 1885,3570 r0 top (schematic designator R101)
R10 "CRCW06030000Z0EA" 0603 2274,458.5 r90 top (schematic designator R94)
R11 "RC0603FR-0712RL" 0603 1671,2690 r270 top (schematic designator R16)
R12 "" 0603 1670,1740 r270 top (schematic designator R105)
R13 "CRCW060347K0JNEA" 0603 2366.76,665.73 r90 top (schematic designator R59)
R14 "RC0603FR-0712RL" 0603 1741,2690 r270 top (schematic designator R89)
R15 "" 0603 1750,1740 r270 top (schematic designator R100)
R16 "CRCW060310K0JNEA" 0603 2744,493.5 r270 bottom (schematic designator R88)
R17 "CRCW060310K0JNEA" 0603 2844,493.5 r270 bottom (schematic designator R106)
R18 "CRCW060310K0JNEA" 0603 2945,493.5 r270 bottom (schematic designator R101)
R19 "" 0603 2242.14,3355 r180 top (schematic designator R35)
R20 "CRCW060310K0JNEA" 0603 3045,493 r270 bottom (schematic designator R121)
R21 "" 0603 2565,3370 r270 top (schematic designator R99)
R22 "WSLP39213L000FEB" RC3921 3045,3570 r0 top (schematic designator R102)
R23 "" 0603 2675,1745 r270 top (schematic designator R83)
R24 "RC0603FR-0712RL" 0603 2679,2676 r270 top (schematic designator R26)
R25 "" 0603 2745,1745 r270 top (schematic designator R22)
R26 "RC0603FR-0712RL" 0603 2759,2676 r270 top (schematic designator R115)
R27 "CRCW06030000Z0EA" 0603 2944,1120 r0 top (schematic designator R119)
R28 "CRCW06030000Z0EA" 0603 2946,977 r0 top (schematic designator R95)
R29 "RG1608P-102-B-T5" 0603 3089,1077.15 r0 top (schematic designator R43)
R30 "RG1608P-102-B-T5" 0603 3089,1007.15 r0 top (schematic designator R44)
R31 "RG1608P-102-B-T5" 0603 3094,942.15 r0 top (schematic designator R45)
R32 "RG1608P-102-B-T5" 0603 3094,872.15 r0 top (schematic designator R46)
R33 "" 0603 3525,3530 r270 top (schematic designator R96)
R34 "RG1608P-102-B-T5" 0603 3275,1370 r270 top
R35 "RG1608P-102-B-T5" 0603 3344,1369.96 r270 top (schematic designator R33)
R39 "CRCW0603160KFKEA" 0603 654,2416 r0 bottom
R40 "RC0603FR-074K7L" 0603 3548,549 r90 top (schematic designator R143)
R41 "RG1608P-102-B-T5" 0603 3549,1364.98 r270 top (schematic designator R40)
R42 "RG1608P-102-B-T5" 0603 3614,1364.98 r270 top (schematic designator R37)
R43 "RC0603FR-074K7L" 0603 3627,549 r90 top (schematic designator R144)
R44 "CRCW0603160KFKEA" 0603 1734,2423 r0 bottom
R45 "RG1608P-102-B-T5" 0603 3689,1364.98 r270 top (schematic designator R29)
R47 "CRCW0603160KFKEA" 0603 2719,2442 r90 bottom
R48 "RG1608P-102-B-T5" 0603 3754,1364.98 r270 top (schematic designator R27)
R50 "RG1608P-102-B-T5" 0603 3914,972.15 r180 top (schematic designator R36)
R51 "RG1608P-102-B-T5" 0603 3914,907.15 r180 top (schematic designator R35)
R52 "CRCW0603160KFKEA" 0603 4775,2421 r0 bottom
R53 "CRCW0603300RJNEA" 0603 4337,831 r0 top (schematic designator R122)
R54 "CRCW0603300RJNEA" 0603 4337,611 r0 top (schematic designator R124)
R55 "" 0603 3760,3510.02 r270 top (schematic designator R50)
R56 "CRCW0603330RJNEA" 0603 4922,182 r90 top (schematic designator R123)
R57 "" 0603 4001,3553 r270 top (schematic designator R43)
R58 "CRCW0603330RJNEA" 0603 5372,187 r90 top (schematic designator R120)
R59 "CRCW08050000Z0EA" 0805_HV#1 4555.72,2943 r270 top (schematic designator R102)
R60 "RC1206FR-071K02L" 1206 4710.72,2973 r0 top (schematic designator R91)
R61 "RC1206FR-072K4L" 1206 4710.72,2828 r0 top (schematic designator R92)
R63 "RC0603FR-0712RL" 0603 4700,2686 r270 top (schematic designator R94)
R64 "" 0603 4720,1726 r270 top (schematic designator R93)
R65 "RC0603FR-0712RL" 0603 4770,2686 r270 top (schematic designator R69)
R66 "" 0603 4785,1726 r270 top (schematic designator R70)
R67 "ERJ-8ENF3323V" 1206 4905,3635 r270 bottom (schematic designator R14)
R68 "ERJ-8ENF3323V" 1206 4904,3438 r270 bottom (schematic designator R66)
R69 "ERJ-8ENF3323V" 1206 4904,3237 r270 bottom (schematic designator R67)
R70 "ERJ-8ENF3323V" 1206 4749,3191 r180 bottom (schematic designator R68)
R71 "CRCW08050000Z0EA" 0805_HV#1 5148.72,2983 r270 top (schematic designator R104)
R72 "RC1206FR-071K02L" 1206 5308.72,3024 r0 top (schematic designator R101)
R73 "RC1206FR-072K4L" 1206 5308.72,2879 r0 top (schematic designator R102)
R74 "RC0603FR-0712RL" 0603 5295,2731 r270 top (schematic designator R105)
R75 "" 0603 5300,1746 r270 top (schematic designator R103)
R76 "CRCW0603300RJNEA" 0603 5618,749 r270 top (schematic designator R47)
R77 "RC0603FR-0712RL" 0603 5370,2731 r270 top (schematic designator R99)
R78 "" 0603 5370,1746 r270 top (schematic designator R100)
R79 "ERJ-8ENF3323V" 1206 5502,3608 r270 bottom (schematic designator R95)
R80 "ERJ-8ENF3323V" 1206 5501,3407 r270 bottom (schematic designator R96)
R81 "ERJ-8ENF3323V" 1206 5502,3207 r270 bottom (schematic designator R97)
R82 "ERJ-8ENF3323V" 1206 5341,3174 r180 bottom (schematic designator R98)
R83 "CRCW08050000Z0EA" 0805_HV#1 5752,2997 r270 top (schematic designator R115)
R84 "RC1206FR-071K02L" 1206 5923,2913 r0 top (schematic designator R112)
R85 "RC1206FR-072K4L" 1206 5923,3040 r0 top (schematic designator R113)
R86 "RC0603FR-0712RL" 0603 5882.73,2725.98 r270 top (schematic designator R116)
R87 "" 0603 5890,1746 r270 top (schematic designator R114)
R88 "" 0603 5955,1746 r270 top (schematic designator R111)
R89 "RC0603FR-0712RL" 0603 5957.73,2725.98 r270 top (schematic designator R110)
R90 "ERJ-8ENF3323V" 1206 6077,3606 r270 bottom (schematic designator R106)
R91 "ERJ-8ENF3323V" 1206 6079,3405 r270 bottom (schematic designator R107)
R92 "ERJ-8ENF3323V" 1206 6079,3207 r270 bottom (schematic designator R108)
R93 "ERJ-8ENF3323V" 1206 5933,3166 r180 bottom (schematic designator R109)
R94 "" 0603 4210,3244 r180 bottom (schematic designator R47)
R95 "RC0603FR-073K16L" 0603 4075,3319 r180 bottom (schematic designator R45)
R97 "CRCW0603160KFKEA" 0603 5344,2425 r0 bottom
R98 "CRCW08050000Z0EA" 0805_HV#2 3656,982 r270 bottom (schematic designator R71)
R99 "" 0603 3227,3102 r180 bottom (schematic designator R98)
R100 "RC0603FR-073K16L" 0603 3049,3211 r180 bottom (schematic designator R97)
R101 "" 0603 2182.64,3101 r180 bottom (schematic designator R39)
R102 "RC0603FR-073K16L" 0603 2032.64,3191 r180 bottom (schematic designator R37)
R103 "" 0603 1180,3100 r180 bottom (schematic designator R38)
R104 "RC0603FR-073K16L" 0603 1030,3190 r180 bottom (schematic designator R117)
R105 "" 0603 460,3150 r0 bottom (schematic designator R40)
R107 "CRCW0603160KFKEA" 0603 5935,2424 r0 bottom
S1 "7914G-1-000E" SW_7914G-1-000E 2595,525 r0 top
T1 "750342271" 760390015 1000,1905 r90 top
T2 "750342271" 760390015 1980,1910 r90 top
T3 "750342271" 760390015 3001,1922 r90 top (schematic designator T4)
T5 "750342271" 760390015 4002,1900.22 r90 top locked
TP1 "TP-5001-BLACK" TH-40#1 615,3835 r0 top (schematic designator TP12)
TP2 "TP-5001-BLACK" TH-40#2 940,3830 r0 top (schematic designator TP11)
TP3 "" TP-040_RND 1060,3355 r90 top (schematic designator TP5)
TP4 "TP-5001-BLACK" TH-40#3 1720,3770 r0 top (schematic designator TP14)
TP5 "TP-5001-BLACK" TH-40#3 2048.39,3770 r0 top (schematic designator TP13)
TP6 "" TP-040_RND 2099,3358 r90 top
TP7 "TP-5001-BLACK" TH-40#3 2880,3770 r0 top (schematic designator TP16)
TP8 "TP-5001-BLACK" TH-40#3 3210,3770 r0 top (schematic designator TP15)
TP9 "" TP-040_RND 3004,1669 r0 top (schematic designator TP10)
TP10 "" TP-040_RND 3152,3357 r0 top (schematic designator TP9)
TP11 "TP-040_RND" TP-040_RND 3495,1488 r0 top (schematic designator TP18)
TP12 "TP-040_RND" TP-040_RND 3382,1489 r0 top (schematic designator TP17)
TP13 "TP-040_RND" TP-040_RND 3842,612 r90 top (schematic designator TP10)
TP15 "TP-040_RND" TP-040_RND 4938,580 r0 top (schematic designator TP9)
TP16 "" TP-040_RND 4100,3494 r0 top (schematic designator TP8)
TP17 "" TP-040_RND 5667,1809 r180 top (schematic designator TP12)
TP18 "TP-040_RND" TP-040_RND 5262,577 r270 bottom (schematic designator TP6)
U1 "AMC1100DUBR" DUB0008A_N 650,2115 r270 top (schematic designator U23)
U2 "SN6501DBV" DBV0005A_N#1 1100,1780 r270 top (schematic designator U5)
U3 "AMC1100DUBR" DUB0008A_N 1710,2115 r270 top (schematic designator U26)
U4 "SN6501DBV" DBV0005A_N#1 2080,1785 r270 top (schematic designator U6)
U5 "AMC1100DUBR" DUB0008A_N 2713.98,2115 r270 top (schematic designator U2)
U6 "SN6501DBV" DBV0005A_N#1 3105,1777 r270 top (schematic designator U12)
U7 "MSP430FR5869RGZ" RGZ0048B 3509,997.15 r270 top (schematic designator U20)
U10 "SN6501DBV" DBV0005A_N#1 4092,1775.22 r270 top (schematic designator U13)
U11 "AMC1100DUBR" DUB0008A_N 4745,2101 r270 top (schematic designator U4)
U12 "AMC1100DUBR" DUB0008A_N 5330,2101 r270 top (schematic designator U21)
U13 "TPS7A6533QKVURQ1" KVU_1 5862,571 r180 top (schematic designator U10)
U14 "AMC1100DUBR" DUB0008A_N 5925,2101 r270 top (schematic designator U24)
U15 "" MSOP8(DGN) 4100,3084 r270 bottom
U16 "TLV70450DBV" DBV0005A_N#2 3670,2934 r90 bottom (schematic designator U18)
U19 "" MSOP8(DGN) 3080.8,2980 r270 bottom (schematic designator U17)
U20 "TLV70450DBV" DBV0005A_N#2 2695,2910 r90 bottom (schematic designator U24)
U21 "" MSOP8(DGN) 2047.64,2976 r270 bottom (schematic designator U8)
U22 "TLV70450DBV" DBV0005A_N#2 1657.64,2895.5 r90 bottom (schematic designator U10)
U23 "TPS7A3001DGNR" MSOP8(DGN) 1045,2975 r270 bottom (schematic designator U7)
U24 "TLV70450DBV" DBV0005A_N#2 660,2895 r90 bottom (schematic designator U9)
Y1 "CMR200T-32.768KDZBT" XTAL_CMR200T 4197.11,1346.55 r0 top
Y2 "ABLS-8.000MHZ-B4-T" XTAL_CSM-7X 4348,1139 r180 top
ZZ1 "" AssemblyNoteLabel 856,6116 r0 top
ZZ2 "" AssemblyNote 856,5956 r0 top (schematic designator ZZ3)
ZZ3 "" AssemblyNote 856,6041 r0 top (schematic designator ZZ2)
ZZ4 "" AssemblyNote 856,5881 r0 top

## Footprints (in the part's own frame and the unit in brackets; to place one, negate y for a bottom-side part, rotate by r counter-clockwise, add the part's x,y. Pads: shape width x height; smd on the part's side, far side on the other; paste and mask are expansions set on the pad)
3M_N2514-6002-RB [mm] "CONN, HEADER, 14 POS, STRGHT GOLD"
  rect 1.4x1.4 / inner round 1.4 / far side rect 1.4x1.4 hole 0.889: 1(-7.62,-1.27)
  round 1.4 hole 0.889: 2(-7.62,1.27) 3(-5.08,-1.27) 4(-5.08,1.27) 5(-2.54,-1.27) 6(-2.54,1.27) 7(0,-1.27) 8(0,1.27) 9(2.54,-1.27) 10(2.54,1.27) 11(5.08,-1.27) 12(5.08,1.27) 13(7.62,-1.27) 14(7.62,1.27)
  round 0.889 hole 0.889 unplated mask+0.127: ""(-11.99,0)
  Multi-Layer keep-out circle w0.025: c-11.99,0 r1.206
  silkscreen extent -12.55,-5.49 12.55,4.52, body extent -12.55,-4.07 12.55,4.52, height 9.91
0603 [mm] "0603 from SM-752 data"
  rect 1x0.95 smd mask+0.102: 1(-0.8,0) 2(0.8,0)
  silkscreen extent -1.52,-0.69 1.52,0.69, body extent -0.87,-0.47 0.87,0.47, height 0.85
0805_HV#1 [mil] "0805 with 30mil clearance between pads"
  rect 50x63 smd mask+4: 1(-40,0) 2(40,0)
  silkscreen extent -74,-40 74,40, body extent -43,-29 43,29, height 43
0805_HV#2 [mil] "0805 with 30mil clearance between pads"
  rect 50x63 smd: 1(-40,0) 2(40,0)
  silkscreen extent -74,-40 74,40, body extent -43,-29 43,29, height 43
1206 [mm] "1206 from SM-752 data"
  rect 1.3x1.85 smd mask+0.102: 1(-1.45,0) 2(1.45,0)
  silkscreen extent -2.4,-1.21 2.4,1.21, body extent -1.7,-0.9 1.7,0.9, height 1.35
1210#1 [mm] "1210 from SM-752 data"
  rect 1.3x2.7 smd mask+0.102: 1(-1.45,0) 2(1.45,0)
  silkscreen extent -2.32,-1.57 2.32,1.57, body extent -1.7,-1.35 1.7,1.35, height 1.35
1210#2 [mm] "1210 from SM-752 data"
  rect 1.3x2.7 smd: 1(-1.45,0) 2(1.45,0)
  silkscreen extent -2.32,-1.57 2.32,1.57, body extent -1.7,-1.35 1.7,1.35, height 1.35
6032-28 [mm] "Medium Density IPC based on Vishay Sprague 293D datasheet."
  rect 2.55x2.3 smd mask+0.102: 1(-2.375,0) 2(2.375,0)
  silkscreen extent -3.96,-1.75 3.2,1.82, body extent -3.15,-1.75 3.15,1.75, height 2.8
760390015 [mm]
  rect 1.27x0.66 smd mask+0.102: 1(0,0) 2(0,-2.54) 3(0,-5.08) 4(9.14,-5.08) 5(9.14,-2.54) 6(9.14,0)
  silkscreen extent -1.72,-6.35 10.2,1.27, body extent -1,-6.4 10.2,1.2, height 4.2
AssemblyNote [mil] "Assembly Note"
AssemblyNoteLabel [mil] "Assembly Note for PCB Labels"
CAP_200mil#1 [mil]
  round 60 hole 32 mask+5: 1(-100,0) 2(100,0)
  silkscreen extent -205,-80 205,80
CAP_200mil#2 [mil]
  round 60 hole 32 mask+5: 1(-100,0)
  round 60 hole 32 mask+4: 2(100,0)
  silkscreen extent -205,-80 205,80
CONN_ED120-2DS [mm] "ONSHORE"
  rect 1.75x1.75 hole 1.25: 1(0,-2.54)
  round 1.75 hole 1.25: 2(0,2.54)
  silkscreen extent -5,-5.6 4,5.12, body extent -5,-5.6 4.15,5.12, height 13.1
DBV0005A_N#1 [mm] "SOT23, 5-Leads, Body 2.9x1.6mm, Pitch 0.95mm, Lead Span 2.8mm, IPC Medium Density"
  rect 1.1x0.65 smd mask+0.102: 1(-1.2,0.95) 2(-1.2,0) 3(-1.2,-0.95) 4(1.2,-0.95) 5(1.2,0.95)
  silkscreen extent -1.9,-1.55 0.25,1.78, body extent -1.42,-1.46 1.42,1.46, height 1.08
DBV0005A_N#2 [mm] "SOT23, 5-Leads, Body 2.9x1.6mm, Pitch 0.95mm, Lead Span 2.8mm, IPC Medium Density"
  rect 1.1x0.65 smd: 1(-1.2,0.95) 2(-1.2,0) 3(-1.2,-0.95) 4(1.2,-0.95) 5(1.2,0.95)
  silkscreen extent -1.47,-1.55 0.25,1.97, body extent -1.42,-1.46 1.42,1.46, height 1.08
DUB0008A_N [mm] "SOP, 8-Leads, Body 9.5x6.62mm, Pitch 2.54mm, IPC Medium Density"
  oval 2.45x0.6 smd mask+0.102: 1(-4.475,3.81) 2(-4.475,1.27) 3(-4.475,-1.27) 4(-4.475,-3.81) 5(4.475,-3.81) 6(4.475,-1.27) 7(4.475,1.27) 8(4.475,3.81)
  silkscreen extent -6.19,-4.8 2.85,4.8, body extent -3.33,-4.77 3.33,4.77, height 4.85
FB0603#1 [mm]
  rect 0.95x1 smd mask+0.102: 1(-0.75,0) 2(0.75,0)
  silkscreen extent -0.8,-0.7 0.8,0.7
FB0603#2 [mm]
  rect 0.95x1 smd: 1(-0.75,0) 2(0.75,0)
  silkscreen extent -0.8,-0.7 0.8,0.7
Fiducial10-20#1 [mm]
  round 1 smd paste+0 mask+0.5: 1(0,0)
  Top Layer keep-out circle w1.178: c0,0 r0.5
Fiducial10-20#2 [mm]
  round 1 smd mask+0.5: 1(0,0)
  Top Layer keep-out circle w1.178: c0,0 r0.5
HDR1X3#1 [mil] "HDR1X3"
  rect 60x60 / inner round 60 / far side rect 60x60 hole 40: 1(0,100)
  round 60 hole 40: 2(0,0) 3(0,-100)
  silkscreen extent -88,-150 50,150, body extent -50,-150 50,150, height 1
HDR1X3#2 [mil] "Connector; Header; 3 Position"
  rect 59.06x59.06 hole 35.43: 1(0,0)
  round 59.06 hole 35.43: 2(100,0) 3(200,0)
  silkscreen extent -50,-50 250,50
KVU_1 [mm]
  rect 1.2x2.8 smd mask+0.102: 1(-2.29,-3.635) 3(2.29,-3.635)
  rect 6.096x6.096 smd mask+0.102: 2(0,3.635)
  silkscreen extent -3.43,-7.16 3.43,7.22
Label_650x200 [mil] "Thermal Transfer Label"
  round 1 on Mech13: 0(0,0)
  silkscreen extent -325,-100 325,100, body extent -326,-101 326,101, height 1
LED0603AA [mil]
  rect 32x32 smd mask+4: 1(-32.48,0) 2(32.48,0)
  silkscreen extent -23,-69 29,16
LED_5MM [mm] "LED, 5MM, RED, TH"
  rect 1.54x1.54 / inner round 1.54 / far side rect 1.54x1.54 hole 1.04: 1(1.27,0)
  round 1.54 hole 1.04: 2(-1.27,0)
  silkscreen extent -2.9,-4.76 2.9,2.9, body extent -2.9,-2.9 2.9,2.9, height 9
MH3.2 [mil]
  round 128 / inner round 142 / far side round 128 hole 128 unplated mask+10: 1(0,0)
  silkscreen extent -120,-120 120,120
MSOP8(DGN) [mil]
  rect 50x15 smd mask+3: 1(-77,38) 2(-77,12.4) 3(-77,-13.2) 4(-77,-38.8) 5(76.6,-38.8) 6(76.6,-13.2) 7(76.6,12.4) 8(76.6,38)
  rect 60x75 smd: 9(0,-0.8)
  silkscreen extent -115,-73 120,105
powerDI123 [mm] "Diodes Inc recommended land pattern, document number DS30628 Rev. 6-2"
  rect 2.2x1.4 smd: 1(-1.275,0)
  rect 0.9x1.4 smd: 2(1.275,0)
  silkscreen extent -3.1,-1.09 1.76,1.09, body extent -2.37,-0.96 1.53,0.97, height 1
RC3921 [mm] "RESISTOR, SMD, 3921"
  rect 2.7x5.45 smd mask+0.102: 1(-4.15,0) 2(4.15,0)
  silkscreen extent -2.45,-2.6 2.45,2.6, body extent -5,-2.6 5,2.6, height 0.93
RGZ0048B [mm] "QFN, 48-Leads, Body 7x7mm, Pitch 0.5mm, Thermal Pad 5.15x5.15mm, TI Recommended"
  oval 0.6x0.24 smd mask+0.076: 1(-3.4,2.75) 2(-3.4,2.25) 3(-3.4,1.75) 4(-3.4,1.25) 5(-3.4,0.75) 6(-3.4,0.25) 7(-3.4,-0.25) 8(-3.4,-0.75) 9(-3.4,-1.25) 10(-3.4,-1.75) 11(-3.4,-2.25) 12(-3.4,-2.75) 25(3.4,-2.75) 26(3.4,-2.25) 27(3.4,-1.75) 28(3.4,-1.25) 29(3.4,-0.75) 30(3.4,-0.25) 31(3.4,0.25) 32(3.4,0.75) 33(3.4,1.25) 34(3.4,1.75) 35(3.4,2.25) 36(3.4,2.75)
  oval 0.24x0.6 smd mask+0.076: 13(-2.75,-3.4) 14(-2.25,-3.4) 15(-1.75,-3.4) 16(-1.25,-3.4) 17(-0.75,-3.4) 18(-0.25,-3.4) 19(0.25,-3.4) 20(0.75,-3.4) 21(1.25,-3.4) 22(1.75,-3.4) 23(2.25,-3.4) 24(2.75,-3.4) 37(2.75,3.4) 38(2.25,3.4) 39(1.75,3.4) 40(1.25,3.4) 41(0.75,3.4) 42(0.25,3.4) 43(-0.25,3.4) 44(-0.75,3.4) 45(-1.25,3.4) 46(-1.75,3.4) 47(-2.25,3.4) 48(-2.75,3.4)
  rect 4.1x4.1 smd paste-2.575 mask+0.102: 49(0,0)
  silkscreen extent -3.72,-3.72 3.72,3.72, body extent -3.57,-3.58 3.58,3.57, height 1.01
SM_RADIAL_5MM [mm] "Nichicon 5x5.8"
  rect 3x1.6 smd mask+0.102: 1(-2.2,0) 2(2.2,0)
  silkscreen extent -3.68,-2.75 2.75,2.75, body extent -2.75,-2.75 2.75,2.75, height 6.1
SOD-123#1 [mm] "On Semi recommended land pattern"
  rect 0.915x1.22 smd mask+0.102: 1(-1.637,0) 2(1.637,0)
  silkscreen extent -2.74,-1.17 2.03,1.17, body extent -1.93,-0.9 1.93,0.9, height 1.35
SOD-123#2 [mm] "On Semi recommended land pattern"
  rect 0.915x1.22 smd: 1(-1.637,0) 2(1.637,0)
  silkscreen extent -2.74,-1.17 2.03,1.17, body extent -1.93,-0.9 1.93,0.9, height 1.35
SON_CSD17571Q2 [mm] "SON, MOSFET, N-CH, 30V, 22A, SON 2X2 MM"
  rect 0.4x0.455 smd mask+0.076: 1(-0.65,-0.923) 2(0,-0.923) 3(0.65,-0.923) 4(0.65,0.923) 5(0,0.923) 6(-0.65,0.923)
  rect 0.4x0.85 smd mask+0.076: 7(0.65,0.096)
  rect 1.05x1.1 smd mask+0.076: 8(-0.325,0)
  silkscreen extent -1.88,-1.09 1.1,1, body extent -1,-1 1,0.97, height 0.85
SOT-323 [mm] "Zetex recommended land pattern.  March 2007"
  rect 0.8x0.6 smd: 1(-0.8,0.65) 2(-0.8,-0.65) 3(0.8,0)
  silkscreen extent -1.78,-1.22 0.77,1.22, body extent -1.13,-1.13 1.12,1.12, height 1.13
SW_7914G-1-000E [mm] "BOURNS"
  rect 1.27x1.27 smd mask+0.102: 1(-1.27,2.75) 2(-1.27,-2.75) 3(1.27,-2.75) 4(1.27,2.75)
  silkscreen extent -2.5,-3.2 2.5,4.04, body extent -2.25,-2.5 2.25,2.5, height 4.49
TH-40#1 [mil]
  round 200 hole 120: 1(0,0)
TH-40#2 [mil]
  round 200 hole 120: 1(0,5)
TH-40#3 [mil]
  round 200 hole 120: 1(0,60)
TI_STACKED_SOLDERMASK_SMALL [mil]
  silkscreen extent -418,-98 418,98
TP-040_RND [mil]
  round 70 / inner round 62 / far side round 62 hole 40: 1(0,0)
  silkscreen extent -45,-45 45,45
TSW-112-07-G-D [mm] "Samtec 100mil, 2x12, 230 mil above insulator"
  rect 1.65x1.65 hole 1.016 mask+0.102: 1(-13.97,-1.27)
  round 1.65 hole 1.016 mask+0.102: 2(-13.97,1.27) 3(-11.43,-1.27) 4(-11.43,1.27) 5(-8.89,-1.27) 6(-8.89,1.27) 7(-6.35,-1.27) 8(-6.35,1.27) 9(-3.81,-1.27) 10(-3.81,1.27) 11(-1.27,-1.27) 12(-1.27,1.27) 13(1.27,-1.27) 14(1.27,1.27) 15(3.81,-1.27) 16(3.81,1.27) 17(6.35,-1.27) 18(6.35,1.27) 19(8.89,-1.27) 20(8.89,1.27) 21(11.43,-1.27) 22(11.43,1.27) 23(13.97,-1.27) 24(13.97,1.27)
  silkscreen extent -16.26,-2.54 15.24,2.54, body extent -15.24,-2.54 15.24,2.54, height 8.38
WURTH_61300211121 [mm] "Header, 2.54mm, 2x1, TH"
  rect 1.65x1.65 hole 1.15: 1(-1.27,0)
  round 1.65 hole 1.15: 2(1.27,0)
  silkscreen extent -2.54,-1.27 2.54,1.6, body extent -2.54,-1.27 2.54,1.27, height 8.54
XTAL_CMR200T [mm] "XTAL, SMD, 3-PIN"
  rect 2.5x1 smd mask+0.102: 1(-5,1.25) 2(-5,-1.25)
  rect 2.5x2.5 smd mask+0.102: 3(2.75,0)
  Top Layer keep-out region: -3.048,-0.946 0.785,-0.946 0.785,0.954 -3.048,0.954
  silkscreen extent -6.96,-0.95 1.13,1.42, body extent -3,-0.95 3,0.95, height 2
XTAL_CSM-7X [mm] "ECS"
  rect 5.5x2 smd mask+0.102: 1(-4.75,0) 2(4.75,0)
  silkscreen extent -8.26,-2.5 6.2,2.5, body extent -5.95,-2.4 5.95,2.4, height 4.3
